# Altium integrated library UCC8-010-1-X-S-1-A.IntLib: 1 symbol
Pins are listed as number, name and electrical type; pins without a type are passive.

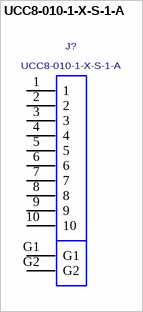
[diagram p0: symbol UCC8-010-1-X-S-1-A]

## UCC8-010-1-X-S-1-A
designator J?
0.8MM UCC8 SOCKET ASSEMBLY.; MANUFACTURER: SAMTEC
footprint UCC8-010-1-X-S-1-A
pins: 1, 2, 3, 4, 5, 6, 7, 8, 9, 10, G1, G2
